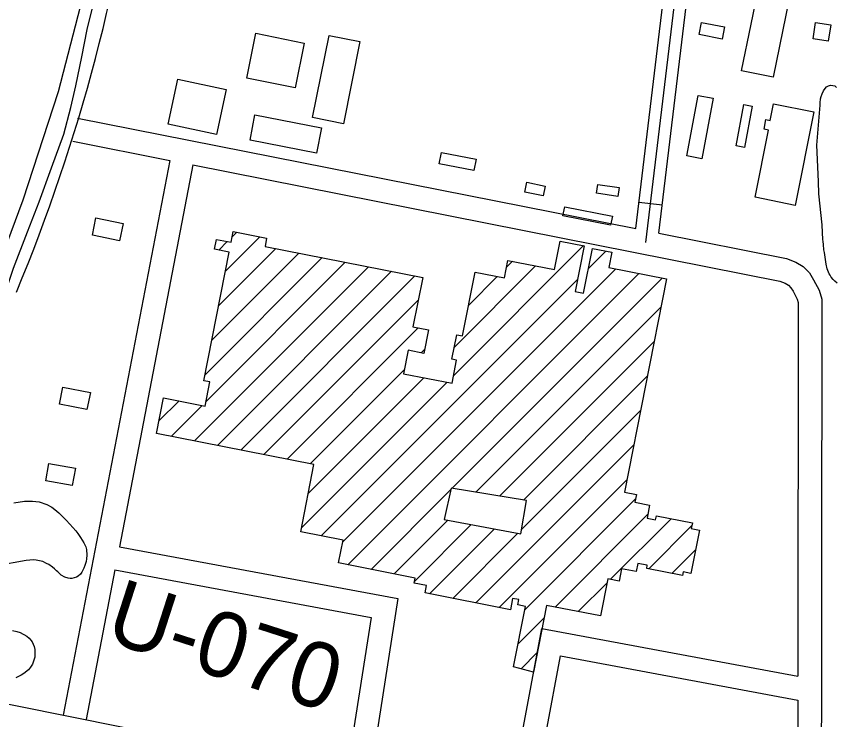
# Model space of a CAD drawing. Extents: x 3297716 to 3335574, y 688621 to 713991.
# Drawn here: x 3324420 to 3325465, y 695588 to 696484 of the extents above; entities that cross this region are included whole.
import ezdxf

# ---------------------------------------------------------------- set-up
doc = ezdxf.new("R2010")
doc.units = 0
for name, color, linetype in [('V-BLDG-OTLN', 7, 'Continuous'), ('V-LEVE-TOET', 7, 'Continuous'), ('V-RIVR-EDGE', 7, 'Continuous'), ('V-RIVR-RANG-IDEN', 7, 'Continuous'), ('V-ROAD-CNTR', 7, 'Continuous'), ('V-SITE-VEGE', 7, 'Continuous'), ('V-TOPO-SHOR', 7, 'Continuous')]:
    doc.layers.add(name, color=color, linetype=linetype)

msp = doc.modelspace()

# ---------------------------------------------------------------- linework, layer by layer
at = {"layer": 'V-BLDG-OTLN'}
for p, q in [((3324694.9, 696203.3), (3324700.4, 696208.8)), ((3324677.8, 696186.1), (3324688.7, 696197.1)), ((3324686.5, 696159.5), (3324730, 696203)), ((3325113, 696197.1), (3325113.6, 696197.7)), ((3324677.8, 696115.4), (3324750.6, 696188.3)), ((3324977.2, 696025.9), (3325143.2, 696191.9)), ((3325149.2, 696162.6), (3325171.6, 696185)), ((3324660.4, 696027.4), (3324809.7, 696176.6)), ((3324669.1, 696071.4), (3324780.1, 696182.5)), ((3324646.8, 695943), (3324868.7, 696165)), ((3324661.6, 695993.2), (3324839.2, 696170.8)), ((3324978.1, 696062.2), (3325082, 696166.1)), ((3325045, 696164.4), (3325052.4, 696171.9)), ((3324676.3, 695937.2), (3324898.3, 696159.2)), ((3324705.9, 695931.4), (3324927.8, 696153.3)), ((3324835.8, 695813.8), (3325184.2, 696162.3)), ((3324842.5, 695785.2), (3325213.8, 696156.4)), ((3324996.6, 696116), (3325033.1, 696152.5)), ((3324808.6, 695822), (3325135.4, 696148.8)), ((3324975.4, 695882.7), (3325243.3, 696150.6)), ((3324735.4, 695925.6), (3324932.1, 696122.3)), ((3325005.7, 695877.7), (3325242.1, 696114.1)), ((3324764.9, 695919.7), (3324932.3, 696087.2)), ((3325036, 695872.6), (3325233.5, 696070.1)), ((3324935.8, 696055.2), (3324940.6, 696060.1)), ((3324794.5, 695913.9), (3324914.6, 696034.1)), ((3324783.2, 695832), (3324969, 696017.8)), ((3324791.9, 695876), (3324939.5, 696023.6)), ((3325066.3, 695867.6), (3325224.8, 696026)), ((3324601.4, 695968.4), (3324627.1, 695994)), ((3324617.3, 695948.9), (3324656.6, 695988.2)), ((3325063.9, 695829.9), (3325216.1, 695982)), ((3325005.9, 695736.5), (3325207.4, 695938)), ((3325035.4, 695730.6), (3325198.7, 695893.9)), ((3324872, 695779.3), (3324974.1, 695881.4)), ((3325068.5, 695728.3), (3325209.6, 695869.4)), ((3325106.8, 695731.3), (3325225.1, 695849.6)), ((3324901.5, 695773.5), (3324970, 695842)), ((3325177.2, 695766.4), (3325254.7, 695843.8)), ((3324927.8, 695764.4), (3324999.7, 695836.4)), ((3324946.8, 695748.1), (3325029.5, 695830.8)), ((3325226.2, 695780), (3325281.3, 695835.1)), ((3324976.4, 695742.3), (3325059.3, 695825.2)), ((3325255.8, 695774.2), (3325286.2, 695804.6)), ((3325136.4, 695725.5), (3325173.1, 695762.2)), ((3325059.7, 695684.2), (3325092.8, 695717.3)), ((3325063.4, 695652.6), (3325084.1, 695673.2))]:
    msp.add_line(p, q, dxfattribs=at)
for points in [[(3325409.3, 696525.7), (3325384.8, 696406.6), (3325344.7, 696414.8), (3325369.2, 696533.9)], [(3325293.7, 696476.3), (3325323, 696470.6), (3325320, 696455.1), (3325290.7, 696460.8)], [(3325439.1, 696476.1), (3325458.4, 696473.3), (3325455.3, 696452.5), (3325436, 696455.4)], [(3324786.8, 696450.1), (3324775.3, 696393.1), (3324713.8, 696405.5), (3324725.2, 696462.5)], [(3324857.8, 696451.9), (3324836.7, 696347.3), (3324797.4, 696355.2), (3324818.5, 696459.8)], [(3324687.2, 696390.9), (3324675.1, 696333.6), (3324613.4, 696346.7), (3324625.5, 696404)], [(3325308.3, 696379.8), (3325293.9, 696302.6), (3325275, 696306.2), (3325289.4, 696383.3)], [(3325347.4, 696371.6), (3325358, 696369.6), (3325348.2, 696316.9), (3325337.7, 696318.9)], [(3325436.9, 696362.3), (3325413, 696243.2), (3325361.9, 696253.5), (3325379.1, 696339.1), (3325373.3, 696340.3), (3325375.8, 696352.6), (3325381.2, 696351.5), (3325385.4, 696372.6)], [(3324724, 696358.5), (3324808.7, 696342.1), (3324802.4, 696309.8), (3324717.7, 696326.2)], [(3324961.7, 696310.4), (3325006.1, 696301.9), (3325003.3, 696287.6), (3324958.9, 696296.1)], [(3325070.9, 696272.6), (3325094.1, 696267.8), (3325091.5, 696255.2), (3325068.3, 696260.1)], [(3325186.9, 696254.7), (3325159.8, 696258.6), (3325161.4, 696269.7), (3325188.5, 696265.9)], [(3325119, 696241.3), (3325179.8, 696229.5), (3325177.6, 696217.9), (3325116.8, 696229.8)], [(3324521.1, 696227.2), (3324555.7, 696220.2), (3324551.2, 696198.2), (3324516.6, 696205.2)], [(3324799.2, 695913), (3324598.3, 695952.6), (3324607.2, 695997.9), (3324660.5, 695987.4), (3324666.5, 696018.1), (3324658.9, 696019.6), (3324691.2, 696183.5), (3324672.2, 696187.2), (3324674.7, 696199.8), (3324693.5, 696196.2), (3324696.2, 696209.7), (3324738.8, 696201.3), (3324736.8, 696191), (3324937.9, 696151.4), (3324925.5, 696088.5), (3324945.4, 696084.6), (3324939.5, 696054.5), (3324919.4, 696058.5), (3324913.6, 696028.7), (3324975.3, 696016.5), (3324981.1, 696045.9), (3324975.1, 696047.1), (3324981.3, 696078.4), (3324988.8, 696076.9), (3325004.9, 696158.1), (3325042.3, 696150.7), (3325046.7, 696173), (3325106, 696161.3), (3325113.2, 696197.8), (3325143.8, 696191.8), (3325132.3, 696133.4), (3325143, 696131.3), (3325154.3, 696188.4), (3325179.3, 696183.4), (3325175.5, 696164), (3325249.1, 696149.5), (3325195.5, 695877.6), (3325210.6, 695874.6), (3325208.6, 695864.8), (3325227.4, 695861.1), (3325224.1, 695844.7), (3325235, 695842.5), (3325236, 695847.5), (3325282, 695838.5), (3325280.5, 695831.3), (3325291, 695829.2), (3325280.1, 695774), (3325270.2, 695776), (3325269.3, 695771.5), (3325223.6, 695780.5), (3325224.4, 695784.6), (3325212.5, 695786.9), (3325210.4, 695776.4), (3325191.7, 695780.1), (3325188.6, 695764.1), (3325174, 695767), (3325164.8, 695719.9), (3325096, 695733.4), (3325079.2, 695648.1), (3325053.9, 695655.2), (3325069.2, 695732.1), (3325059.1, 695734.1), (3325060.4, 695740.7), (3325052.6, 695742.3), (3325049.7, 695727.8), (3324941, 695749.3), (3324942.8, 695758.6), (3324927.2, 695761.7), (3324928.5, 695768.2), (3324830.6, 695787.5), (3324836.3, 695816.5), (3324782.3, 695827.1)], [(3324478.8, 696011.4), (3324514, 696004.5), (3324509.7, 695982.9), (3324474.6, 695989.8)], [(3324461.1, 695914.3), (3324494.9, 695908.3), (3324490.9, 695886), (3324457.2, 695892)], [(3324974.4, 695882.9), (3324965.4, 695842.8), (3325063, 695824.5), (3325070.3, 695866.9)]]:
    msp.add_lwpolyline(points, close=True, dxfattribs=at)
at = {"layer": 'V-LEVE-TOET'}
msp.add_lwpolyline([(3324322.6, 696027.6), (3324383.1, 696130.1), (3324428.1, 696250.4), (3324473.4, 696388.4), (3324501.4, 696496.6), (3324523.2, 696624.9), (3324550.4, 696762.7), (3324571.3, 696899.6), (3324592.3, 697085.8), (3324607.4, 697236.4), (3324624.6, 697352.3), (3324638.1, 697438.1), (3324652.5, 697525.7), (3324668.2, 697669.4), (3324686.1, 697792.1), (3324708.4, 697921.3), (3324730.8, 698074.1), (3324752.9, 698217.5), (3324776.4, 698356.9), (3324801.7, 698466), (3324842.9, 698645.1), (3324895.6, 698812.7), (3324938.8, 698954), (3324980.6, 699092.3)], dxfattribs=at)
at = {"layer": 'V-RIVR-EDGE'}
msp.add_spline([(3322948.4, 694020.9), (3322949.4, 694024.6), (3322957.6, 694042.5), (3322967, 694074.2), (3322979.9, 694110.3), (3322999, 694165.7), (3323019.3, 694218.8), (3323047.4, 694293.1), (3323065, 694340.8), (3323068.5, 694359.8), (3323070.1, 694370.3), (3323070.9, 694381.5), (3323071.4, 694406.3), (3323072.9, 694416.4), (3323078.8, 694426.9), (3323084.2, 694438.9), (3323087.4, 694448.9), (3323090.1, 694465.6), (3323090.5, 694472.2), (3323089.4, 694480.3), (3323089.4, 694485.4), (3323093.7, 694496.2), (3323102.6, 694511), (3323113.5, 694521.4), (3323114.3, 694527.2), (3323113.9, 694538.5), (3323114.8, 694553.6), (3323118.7, 694578), (3323123, 694590), (3323132, 694609.4), (3323139.7, 694619.4), (3323140.9, 694623.3), (3323134.3, 694627.2), (3323134.3, 694629.9), (3323141.4, 694643.5), (3323148, 694650.1), (3323149.1, 694657.8), (3323151.9, 694667.5), (3323157, 694681.4), (3323161.7, 694700.8), (3323165.6, 694719.4), (3323168.7, 694729.1), (3323174.9, 694741.1), (3323179.2, 694750.4), (3323184.3, 694764), (3323190.2, 694773.7), (3323189.4, 694781.4), (3323190.6, 694787.6), (3323200.3, 694810.1), (3323212.4, 694839.9), (3323221, 694868.2), (3323223.8, 694883.7), (3323229.6, 694903.1), (3323232.8, 694917.4), (3323234.8, 694930.6), (3323239.1, 694944.6), (3323242.2, 694953.5), (3323245.7, 694969), (3323248.8, 694981.4), (3323256.3, 695000.8), (3323259.4, 695007), (3323262.1, 695010.8), (3323261, 695021.3), (3323261.4, 695030.6), (3323262.6, 695039.5), (3323266.1, 695047.3), (3323266.5, 695051.9), (3323266.1, 695067), (3323267.3, 695083.3), (3323269.7, 695102.7), (3323271.3, 695115.5), (3323274.8, 695126), (3323280.2, 695129.8), (3323284.9, 695138.4), (3323287.3, 695149.2), (3323288.8, 695163.6), (3323288.9, 695169.4), (3323285.8, 695172.5), (3323285.8, 695176.7), (3323290.1, 695184.1), (3323291.2, 695191.9), (3323304.1, 695221.7), (3323311.1, 695239.5), (3323319.8, 695275.5), (3323326.1, 695314.3), (3323328.5, 695355.8), (3323328.2, 695389.5), (3323329, 695403.5), (3323333.3, 695415.9), (3323336.8, 695424.8), (3323336.8, 695432.2), (3323336.8, 695436.4), (3323334.5, 695438), (3323333.7, 695441.9), (3323334.1, 695448.5), (3323336.1, 695450.8), (3323336.5, 695462), (3323335, 695467.5), (3323336.5, 695474.1), (3323337.7, 695483.4), (3323338.9, 695489.6), (3323338.9, 695501.6), (3323339.7, 695509), (3323344.4, 695509.3), (3323347.5, 695521.7), (3323348.7, 695527.5), (3323352.2, 695529.5), (3323353.7, 695534.1), (3323353.8, 695535.7), (3323351.8, 695536.8), (3323349.5, 695546.2), (3323347.2, 695564.8), (3323348.4, 695576), (3323350.8, 695580.3), (3323348.8, 695584.2), (3323346.1, 695590.8), (3323352.4, 695616), (3323351.6, 695618.7), (3323350.5, 695619.8), (3323349.7, 695636.1), (3323350.5, 695641.9), (3323355.6, 695646.6), (3323358.3, 695659.4), (3323360.3, 695663.6), (3323363.4, 695663.2), (3323363.4, 695657.4), (3323367.2, 695648.9), (3323370.3, 695649.7), (3323370.7, 695664), (3323374.3, 695670.6), (3323381.3, 695680.3), (3323382, 695687.2), (3323388.7, 695710.9), (3323396.5, 695736.5), (3323397.7, 695745.4), (3323398.5, 695753.5), (3323397.7, 695759.3), (3323393.9, 695765.9), (3323394.3, 695773.7), (3323399.3, 695782.6), (3323407.1, 695785.3), (3323418, 695785.3), (3323418, 695788.8), (3323420.7, 695801.2), (3323422.3, 695809.3), (3323424.6, 695816.7), (3323424.7, 695827.9), (3323425.8, 695831.4), (3323428.6, 695834.1), (3323437.5, 695832.1), (3323439, 695835.2), (3323431.7, 695839.5), (3323429.8, 695847.3), (3323429.8, 695857.4), (3323430.6, 695869.8), (3323433.7, 695876), (3323435.3, 695879.8), (3323433.7, 695887.6), (3323434.9, 695893), (3323438.4, 695898.8), (3323445.8, 695905.8), (3323452.8, 695910.4), (3323454.3, 695912.8), (3323453.2, 695917.4), (3323447.4, 695922.9), (3323447.4, 695927.5), (3323447.4, 695932.2), (3323452.1, 695947.3), (3323456, 695967.4), (3323463.1, 695984.5), (3323466.9, 695989.5), (3323475.1, 695994.2), (3323476.3, 695998), (3323476.3, 696003.8), (3323479, 696010.4), (3323484.9, 696018.9), (3323492.2, 696027.1), (3323500.4, 696034.4), (3323505.9, 696046.8), (3323509, 696051.5), (3323516.4, 696056.5), (3323519.5, 696063.1), (3323526.1, 696068.1), (3323531.5, 696076.2), (3323536.2, 696085.5), (3323536.2, 696090.6), (3323532, 696097.9), (3323530.4, 696102.2), (3323530.4, 696104.5), (3323533.9, 696106.9), (3323544.1, 696129.3), (3323548.7, 696135.9), (3323553.4, 696149.9), (3323555.4, 696158), (3323554.6, 696165.4), (3323556.6, 696170.4), (3323558.2, 696173.9), (3323559.7, 696179.3), (3323566.3, 696195.2), (3323569.9, 696204.9), (3323570.3, 696214.2), (3323571.8, 696217.3), (3323578, 696218), (3323583.1, 696221.1), (3323583.9, 696229.3), (3323588.6, 696240.9), (3323595.2, 696250.2), (3323599.5, 696254.4), (3323606.4, 696256.8), (3323608.8, 696263.3), (3323619.4, 696304), (3323636.9, 696361), (3323653.4, 696425.7), (3323674.5, 696502.8), (3323685.1, 696538.5), (3323701.1, 696582.3), (3323710.9, 696613.7), (3323717.2, 696648.2), (3323723.8, 696687.3), (3323726.2, 696709.8), (3323735.2, 696743.9), (3323756.7, 696804), (3323773.9, 696859), (3323781.4, 696890), (3323782.9, 696896.6), (3323786, 696898.9), (3323786.4, 696902), (3323784.9, 696905.1), (3323782.2, 696907.8), (3323782.6, 696913.6), (3323780.6, 696915.6), (3323779.1, 696916.4), (3323779.1, 696925.3), (3323780.3, 696940.8), (3323785.4, 696958.2), (3323787.8, 696967.9), (3323789.7, 696967.5), (3323796.3, 696966.7), (3323797.8, 696969.1), (3323798.2, 696973.7), (3323801.4, 696993.9), (3323801.4, 697006.7), (3323801.5, 697025.3), (3323803.5, 697042.7), (3323803.9, 697051.7), (3323803.9, 697055.1), (3323801.2, 697059), (3323800.4, 697062.1), (3323802, 697063.7), (3323807, 697063.7), (3323807.4, 697067.2), (3323807.4, 697077.6), (3323807.8, 697088.5), (3323810.2, 697098.9), (3323812.5, 697109), (3323818, 697108.6), (3323823.4, 697109.4), (3323824.6, 697110.9), (3323821.5, 697113.7), (3323821.1, 697116.8), (3323819.9, 697117.5), (3323809.8, 697121.1), (3323809.5, 697122.6), (3323809.5, 697125.7), (3323818.4, 697143.9), (3323821.6, 697156.7), (3323825.5, 697157.5), (3323830.9, 697157.8), (3323834, 697159.8), (3323834, 697162.1), (3323830.1, 697164.1), (3323823.5, 697164.1), (3323823.1, 697167.2), (3323823.2, 697169.9), (3323825.1, 697171.4), (3323827.8, 697171.8), (3323829.4, 697172.2), (3323830.1, 697174.5), (3323831.7, 697179.2), (3323834, 697181.9), (3323834.1, 697187.3), (3323836.4, 697202), (3323835.3, 697205.9), (3323827.1, 697211), (3323823.3, 697216), (3323822.9, 697220.3), (3323824.5, 697225), (3323826.8, 697233.9), (3323831.5, 697242.8), (3323836.6, 697259.4), (3323841.3, 697282.7), (3323847.5, 697305.9), (3323851.8, 697323), (3323857.3, 697337.7), (3323865.1, 697352.4), (3323867.8, 697363.7), (3323867.1, 697371.4), (3323864.8, 697379.6), (3323867.1, 697392), (3323875.4, 697419.5), (3323883.1, 697434.2), (3323896.8, 697457.5), (3323907.3, 697471.8), (3323915.1, 697484.9), (3323917.8, 697500.1), (3323925.6, 697525.6), (3323933.8, 697546.2), (3323940.1, 697560.9), (3323942, 697569), (3323946.7, 697581.8), (3323953.3, 697596.5), (3323965.8, 697625.6), (3323975.6, 697647.3), (3323979.1, 697663.2), (3323983.4, 697679.1), (3323992, 697703.5), (3323996.7, 697721.7), (3324001.8, 697731), (3324007.6, 697740.3), (3324011.5, 697757.7), (3324016.2, 697778.3), (3324014.8, 697805.4), (3324012.9, 697825.6), (3324013.7, 697833.7), (3324020.7, 697864.7), (3324032.9, 697932.6), (3324038.4, 697957), (3324042.7, 697965.9), (3324046.6, 697972.5), (3324050.9, 697985.3), (3324055.9, 697991.8), (3324055.9, 697996.1), (3324055.6, 698003.5), (3324056.8, 698026.7), (3324061.1, 698060.5), (3324067.8, 698100.8), (3324075.3, 698139.2), (3324081.5, 698157.4), (3324088.6, 698168.6), (3324090.9, 698174.4), (3324094.8, 698187.6), (3324095.6, 698203.9), (3324097.3, 698239.2), (3324100.4, 698272.1), (3324108.3, 698319.4), (3324118.9, 698370.6), (3324132.6, 698414.4), (3324146.3, 698484.1), (3324153, 698511.3), (3324155.7, 698522.1), (3324161.6, 698527.9), (3324167.8, 698539.1), (3324172.5, 698553.1), (3324172.5, 698562.8), (3324169.4, 698571.3), (3324162.1, 698581.8), (3324160.9, 698585.7), (3324161, 698588.8), (3324167.2, 698626.4), (3324180.2, 698695.8), (3324201.8, 698795.8), (3324223.7, 698871.4), (3324235.4, 698911.3), (3324246.8, 698941.1), (3324253, 698969.4), (3324262.8, 699002.3), (3324270.2, 699013.6), (3324276.8, 699026), (3324280.3, 699038.4), (3324280.4, 699048), (3324280, 699057.4), (3324275.8, 699065.1), (3324274.6, 699081.4), (3324272.4, 699102), (3324269.7, 699123.3), (3324271.7, 699143.1), (3324274.8, 699166.3), (3324284.6, 699202), (3324289.3, 699228), (3324289, 699240.8), (3324287.4, 699246.2), (3324284.4, 699249.7), (3324270.4, 699255.5), (3324268.5, 699260.2), (3324271.2, 699271.8), (3324280.5, 699269.9), (3324281.3, 699272.6), (3324283.7, 699285.4), (3324286.4, 699306.7), (3324288.4, 699322.6), (3324292.3, 699342.4), (3324299.4, 699366), (3324314.3, 699435), (3324317.8, 699439.6), (3324326.7, 699439.6), (3324329.8, 699441.9), (3324329.8, 699448.1), (3324329.8, 699451.2), (3324334.9, 699455.1), (3324345.4, 699462.1), (3324350.1, 699474.8), (3324350.1, 699488), (3324350.1, 699497.3), (3324354, 699516.7), (3324362.6, 699545.4), (3324370.5, 699567.1), (3324371.6, 699575.6), (3324363.5, 699587.3), (3324361.2, 699591.5), (3324361.2, 699596.2), (3324361.2, 699600.9), (3324374.9, 699641.9), (3324390.6, 699699.3), (3324404.3, 699747.3), (3324409, 699779.5), (3324416.8, 699821.8), (3324421.2, 699840), (3324418.9, 699854.3), (3324419.3, 699864), (3324419.3, 699866.7), (3324417, 699867.9), (3324409.6, 699870.6), (3324408.8, 699872.6), (3324409.6, 699875.7), (3324415.1, 699888.9), (3324417, 699903.6), (3324417.1, 699913.3), (3324415.2, 699920.7), (3324412.4, 699924.2), (3324416.8, 699940.8), (3324421, 699938.1), (3324424.9, 699958.6), (3324427, 699990), (3324429.7, 700014.9), (3324433.7, 700045.9), (3324439.6, 700081.1), (3324442.8, 700115.3), (3324446.3, 700122.6), (3324447.1, 700129.2), (3324446.7, 700149.8), (3324449.5, 700177.3), (3324457, 700218.8), (3324465.2, 700252.5), (3324468.8, 700275), (3324468.8, 700299), (3324471.6, 700338.6), (3324481.5, 700399.4), (3324496.1, 700487.8), (3324505.1, 700552.6), (3324518.2, 700651), (3324528.8, 700729.3), (3324548.9, 700827), (3324554.7, 700855.7), (3324559, 700860.7), (3324565.2, 700868.1), (3324568.4, 700880.1), (3324568.4, 700885.1), (3324563.8, 700891.4), (3324563.4, 700895.2), (3324563.4, 700898.7), (3324568.1, 700920), (3324578.2, 700949.9), (3324578.7, 700961.9), (3324576.8, 700982.1), (3324579.6, 701010.4), (3324583.1, 701034), (3324587.8, 701041), (3324591.3, 701043.7), (3324604.5, 701048.3), (3324610.3, 701052.6), (3324613, 701058.8), (3324615.8, 701066.1), (3324624.8, 701101.8), (3324630.7, 701157.6), (3324636.7, 701222.4), (3324632.9, 701263.5), (3324633.8, 701299.1), (3324637, 701329.4), (3324648, 701383.3), (3324651.1, 701404.2), (3324653.5, 701421.3), (3324659.4, 701453.4), (3324663.7, 701482.9), (3324662.6, 701496.9), (3324663, 701509.7), (3324668.1, 701528.3), (3324671.2, 701548), (3324672.1, 701564.7), (3324673.3, 701584.5), (3324678.4, 701598), (3324681.1, 701624.8), (3324682.3, 701636.8), (3324688.2, 701645.3), (3324695.9, 701653.8), (3324697.1, 701662), (3324700.3, 701692.2)], degree=3, dxfattribs=at)
at = {"layer": 'V-ROAD-CNTR'}
msp.add_line((3325213.8, 696247.2), (3325243.6, 696243.7), dxfattribs=at)
for points in [[(3325222.7, 696195.8), (3325333.1, 697114.9), (3325339, 697132.2), (3325349.3, 697142.7), (3325373.3, 697155.9), (3325405.2, 697166.1), (3325442.1, 697169), (3325474.8, 697168.8), (3325799.4, 697138.7), (3325811.6, 697136.9), (3325819.1, 697133.1), (3325823.6, 697128), (3325828.1, 697119.8), (3325829.8, 697107.6), (3325808.7, 696271), (3325805.3, 696075.4)], [(3325239.3, 696207.8), (3325347.8, 697111.5), (3325352.1, 697124.1), (3325358.4, 697130.6), (3325379.3, 697142), (3325408.1, 697151.3), (3325442.6, 697154), (3325474.1, 697153.8)], [(3325209.7, 696213.7), (3325319.3, 697126.3)], [(3324497.5, 696354.4), (3325209.7, 696213.7)], [(3324491.7, 696325), (3324615.4, 696300.5)], [(3324615.4, 696300.5), (3324479.2, 695593.6)], [(3324644.9, 696294.7), (3324551.1, 695808)], [(3324644.9, 696294.7), (3325393.5, 696146.8), (3325400.1, 696144.1), (3325404.4, 696141.4), (3325407.6, 696138.3), (3325410.3, 696133.8), (3325415.7, 696123.7), (3325416.9, 696119.4), (3325416.5, 695643)], [(3325239.3, 696207.8), (3325402, 696175.7), (3325413.9, 696170.9), (3325423, 696165.1), (3325431.2, 696157.3), (3325436.4, 696148.5), (3325443.7, 696135), (3325446.9, 696123.6), (3325446.3, 695403.6)], [(3324551.1, 695808), (3324906.3, 695742), (3324870.7, 695515.6)], [(3324545.4, 695778.6), (3324508.7, 695587.9)], [(3324545.4, 695778.6), (3324872.1, 695717.9), (3324841.1, 695520.2)], [(3325047.6, 695479.1), (3325089.8, 695703.9), (3325416.5, 695643)], [(3325077.1, 695473.6), (3325113.8, 695668.9), (3325416.5, 695612.5)], [(3324219.5, 695645.9), (3325223.2, 695444), (3326063, 695280.8)], [(3325416.5, 695612.5), (3325416.3, 695403.6)]]:
    msp.add_lwpolyline(points, dxfattribs=at)
msp.add_arc((3322329.6, 697006), 2265.2, 337.322, 353.2434, dxfattribs=at)
at = {"layer": 'V-SITE-VEGE'}
for points in [[(3325466.4, 696144.2), (3325463.6, 696146.5), (3325461.4, 696148.8), (3325459.1, 696151.7), (3325457.5, 696154.2), (3325456.5, 696156.1), (3325454, 696162.5), (3325452.5, 696168.2), (3325450.3, 696183.1), (3325449.7, 696186.6), (3325449.1, 696193.4), (3325448.6, 696197), (3325448.5, 696199.9), (3325447.7, 696208.8), (3325447.5, 696218.5), (3325443.1, 696258.1), (3325442.7, 696273.7), (3325440.8, 696320), (3325444.8, 696371), (3325444.8, 696373.8), (3325445.5, 696378.8), (3325446, 696382), (3325447.3, 696385.5), (3325449.1, 696389.3), (3325451.3, 696392.2), (3325453, 696394.1), (3325455.5, 696395.5), (3325457.9, 696396.3), (3325461.2, 696396.1), (3325463.7, 696395.4), (3325465.6, 696393.3)], [(3324416.2, 695864.1), (3324430, 695866), (3324440.2, 695866.3), (3324448.7, 695865.3), (3324458.7, 695862.1), (3324464.9, 695858.5), (3324468.8, 695855.6), (3324473.7, 695851.3), (3324480.7, 695844.7), (3324483.3, 695841.8), (3324488, 695837), (3324495.4, 695828.3), (3324498, 695825), (3324501.5, 695820), (3324503.7, 695816.7), (3324505.7, 695813.1), (3324508.1, 695807.9), (3324509.1, 695804.8), (3324509.4, 695797.4), (3324509.1, 695792.9), (3324508.6, 695789.5), (3324507, 695784.2), (3324505.6, 695780.6), (3324503.2, 695775.9), (3324501.6, 695773.3), (3324498.5, 695770.5), (3324496.2, 695769.2)], [(3324465.9, 695782), (3324461.1, 695785.5), (3324458.1, 695786.9), (3324453.4, 695789.3), (3324444.7, 695791.2), (3324441.3, 695791.3), (3324432, 695790.7), (3324393.8, 695783.8)], [(3324496.2, 695769.2), (3324493.4, 695768.3), (3324490.3, 695767.8), (3324488.2, 695767.7), (3324485.6, 695768.1), (3324481.4, 695769.5), (3324476.9, 695771.7), (3324475.1, 695773.5), (3324472.5, 695776), (3324470.8, 695777.4), (3324468.4, 695779.9), (3324465.9, 695782)], [(3324414.7, 695701.3), (3324420.4, 695700), (3324424.5, 695698.6), (3324432.8, 695694.3), (3324436.1, 695691.5), (3324438, 695689.2), (3324439.6, 695686.7), (3324442.2, 695680.8), (3324443, 695677.3), (3324443.3, 695672.4), (3324443, 695667.5), (3324442.2, 695665), (3324441.2, 695660.9), (3324440, 695658.4), (3324437.8, 695654.7), (3324434.9, 695651.1), (3324429.3, 695646.7), (3324425.8, 695644.5), (3324419.1, 695641.2)]]:
    msp.add_lwpolyline(points, dxfattribs=at)
at = {"layer": 'V-TOPO-SHOR'}
msp.add_lwpolyline([(3324365, 696030.9), (3324402.6, 696124.1), (3324415.9, 696163.2), (3324433.7, 696209.4), (3324448.8, 696247.8), (3324464.6, 696291), (3324480, 696333.8), (3324488.9, 696368), (3324495.6, 696395.4), (3324503.2, 696432.7), (3324510.1, 696467.3), (3324519, 696503.6), (3324528.6, 696549.8), (3324535.9, 696585), (3324543.1, 696622.7), (3324555, 696686.3), (3324566.8, 696749.6), (3324581.2, 696832.1), (3324594, 696913.5), (3324601.4, 696972.3), (3324630.9, 697144), (3324663.9, 697356.5)], dxfattribs=at)

# ---------------------------------------------------------------- texts
at = {"layer": 'V-RIVR-RANG-IDEN'}
msp.add_text('U-070', height=83, rotation=342.0923, dxfattribs=at).set_placement((3324529.9, 695689.4))

doc.saveas('drawing.dxf')
